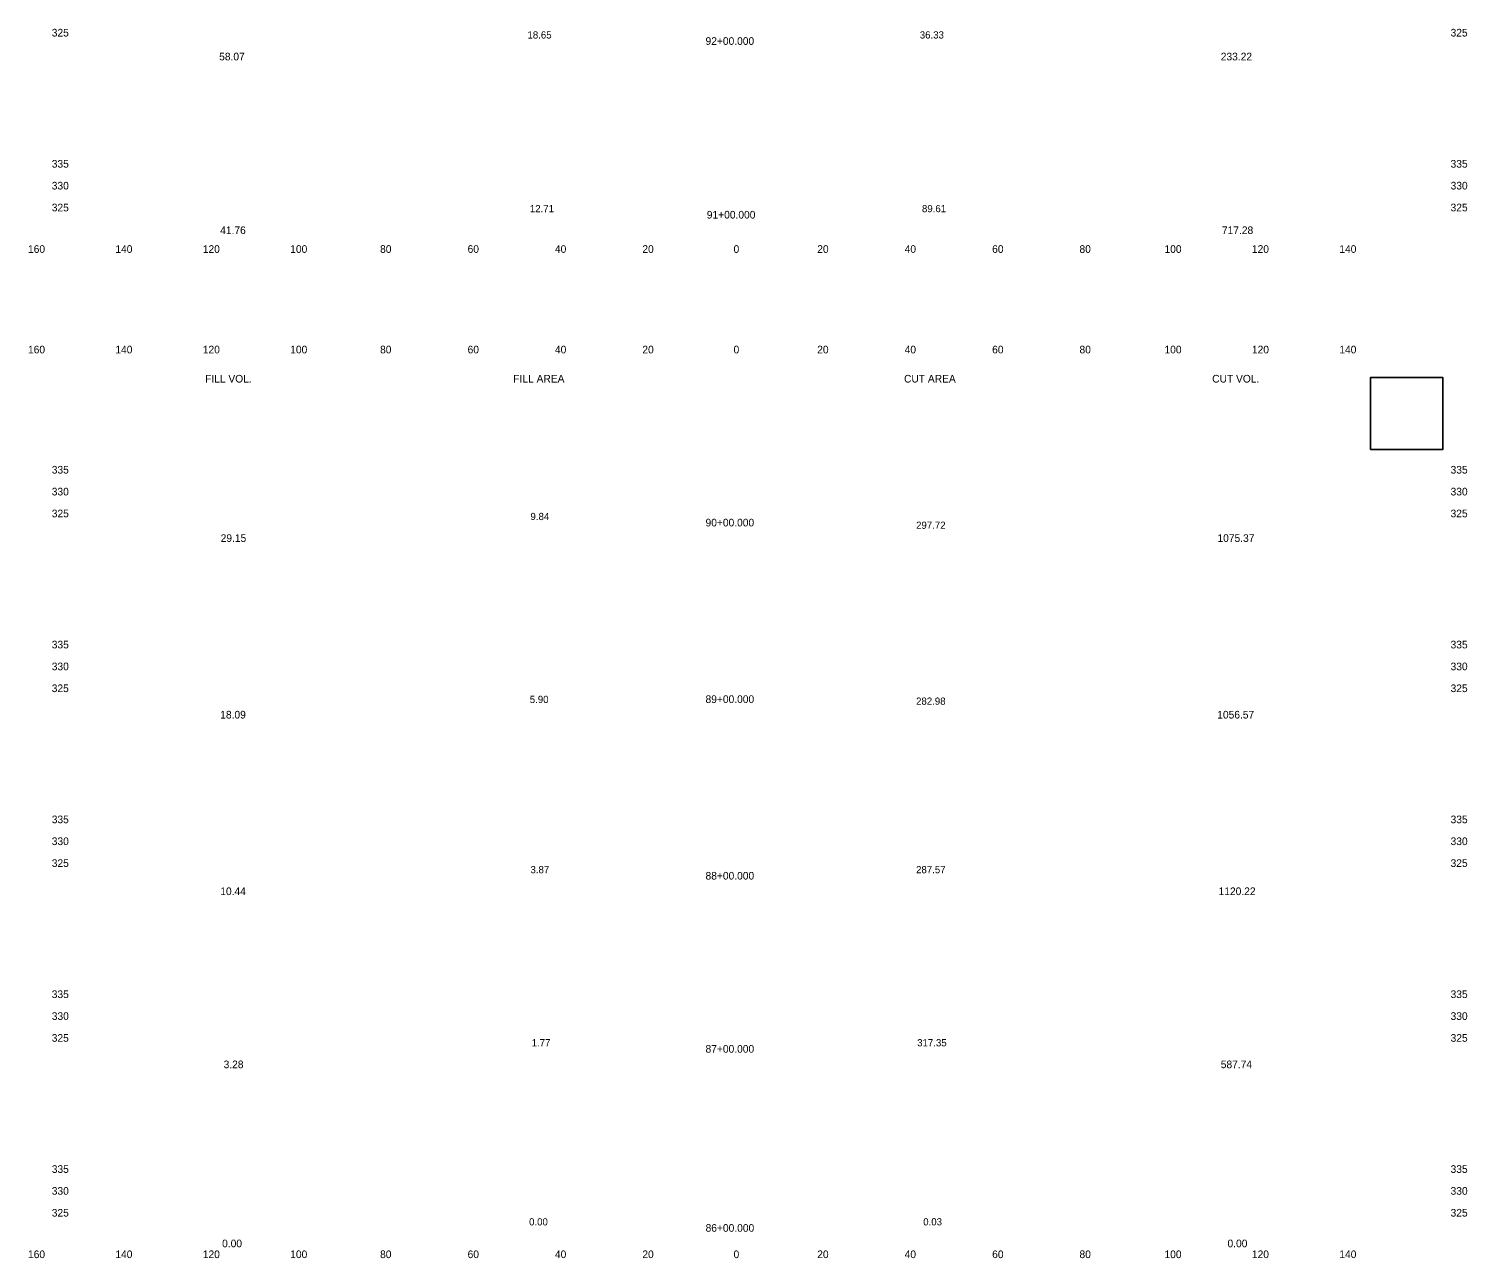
# Model space of a CAD drawing. Extents: x 21477 to 21806, y 6470 to 11049.
# Drawn here: x 21477.1 to 21806.1, y 6470.3 to 6751.6 of the extents above; entities that cross this region are included whole.
import ezdxf

# ---------------------------------------------------------------- set-up
doc = ezdxf.new("R2010")
doc.units = 0
for name, color, linetype in [('SHEET_CONSULTANT_STAMP', 7, 'Continuous'), ('XS_SHEET_EW_TX_AREA', 7, 'Continuous'), ('XS_SHEET_EW_TX_VOLUME', 7, 'Continuous'), ('XS_SHEET_LABELS_ELEVATION', 7, 'Continuous'), ('XS_SHEET_LABELS_OFFSET', 7, 'Continuous'), ('XS_SHEET_LABELS_STATION', 7, 'Continuous'), ('XS_SHEET_TX', 7, 'Continuous')]:
    doc.layers.add(name, color=color, linetype=linetype)

msp = doc.modelspace()

# ---------------------------------------------------------------- linework, layer by layer
at = {"layer": 'SHEET_CONSULTANT_STAMP'}
msp.add_lwpolyline([(21784.04, 6655.34), (21800.54, 6655.34), (21800.54, 6671.84), (21784.04, 6671.84)], close=True, dxfattribs=at)

# ---------------------------------------------------------------- texts
at = {"layer": 'XS_SHEET_EW_TX_AREA'}
for s, p in [(' 18.65 ', (21590.55, 6749.38)), (' 36.33 ', (21680.3, 6749.38)), (' 12.71 ', (21591.1, 6709.64)), (' 89.61 ', (21680.8, 6709.64)), (' 9.84 ', (21591.24, 6639.2)), (' 297.72 ', (21679.45, 6637.2)), (' 5.90 ', (21591.08, 6597.35)), (' 282.98 ', (21679.45, 6596.95)), (' 3.87 ', (21591.24, 6558.4)), (' 287.57 ', (21679.45, 6558.4)), (' 1.77 ', (21591.5, 6518.79)), (' 317.35 ', (21679.7, 6518.79)), (' 0.00 ', (21590.92, 6477.82)), (' 0.03 ', (21681.09, 6477.82))]:
    msp.add_text(s, height=1.65, dxfattribs=at).set_placement(p)
at = {"layer": 'XS_SHEET_EW_TX_VOLUME'}
for s, p in [(' 58.07 ', (21519.98, 6744.38)), (' 233.22 ', (21749.12, 6744.38)), (' 41.76 ', (21520.22, 6704.64)), (' 717.28 ', (21749.38, 6704.64)), (' 29.15 ', (21520.33, 6634.2)), (' 1075.37 ', (21748.36, 6634.2)), (' 18.09 ', (21520.23, 6593.8)), (' 1056.57 ', (21748.31, 6593.8)), (' 10.44 ', (21520.24, 6553.4)), (' 1120.22 ', (21748.62, 6553.4)), (' 3.28 ', (21521, 6513.79)), (' 587.74 ', (21749.12, 6513.79)), (' 0.00 ', (21520.66, 6472.82)), (' 0.00 ', (21750.66, 6472.82))]:
    msp.add_text(s, height=1.75, dxfattribs=at).set_placement(p)
at = {"layer": 'XS_SHEET_LABELS_ELEVATION'}
for s, p in [('  325  ', (21481.04, 6749.84)), ('  325  ', (21801.04, 6749.84)), ('  335  ', (21481.04, 6719.84)), ('  335  ', (21801.04, 6719.84)), ('  330  ', (21481.04, 6714.84)), ('  330  ', (21801.04, 6714.84)), ('  325  ', (21481.04, 6709.84)), ('  325  ', (21801.04, 6709.84)), ('  335  ', (21481.04, 6649.84)), ('  335  ', (21801.04, 6649.84)), ('  330  ', (21481.04, 6644.84)), ('  330  ', (21801.04, 6644.84)), ('  325  ', (21481.04, 6639.84)), ('  325  ', (21801.04, 6639.84)), ('  335  ', (21481.04, 6609.84)), ('  335  ', (21801.04, 6609.84)), ('  330  ', (21481.04, 6604.84)), ('  330  ', (21801.04, 6604.84)), ('  325  ', (21481.04, 6599.84)), ('  325  ', (21801.04, 6599.84)), ('  335  ', (21481.04, 6569.84)), ('  335  ', (21801.04, 6569.84)), ('  330  ', (21481.04, 6564.84)), ('  330  ', (21801.04, 6564.84)), ('  325  ', (21481.04, 6559.84)), ('  325  ', (21801.04, 6559.84)), ('  335  ', (21481.04, 6529.84)), ('  335  ', (21801.04, 6529.84)), ('  330  ', (21481.04, 6524.84)), ('  330  ', (21801.04, 6524.84)), ('  325  ', (21481.04, 6519.84)), ('  325  ', (21801.04, 6519.84)), ('  335  ', (21481.04, 6489.84)), ('  335  ', (21801.04, 6489.84)), ('  330  ', (21481.04, 6484.84)), ('  330  ', (21801.04, 6484.84)), ('  325  ', (21481.04, 6479.84)), ('  325  ', (21801.04, 6479.84))]:
    msp.add_text(s, height=1.75, dxfattribs=at).set_placement(p)
at = {"layer": 'XS_SHEET_LABELS_OFFSET'}
for s, p in [('  160  ', (21475.6, 6700.34)), ('  140  ', (21495.59, 6700.34)), ('  120  ', (21515.59, 6700.34)), ('  100  ', (21535.59, 6700.34)), ('  80  ', (21556.15, 6700.34)), ('  60  ', (21576.17, 6700.34)), ('  40  ', (21596.15, 6700.34)), ('  20  ', (21616.15, 6700.34)), ('  0  ', (21637.01, 6700.34)), ('  0  ', (21637.01, 6700.34)), ('  20  ', (21656.15, 6700.34)), ('  40  ', (21676.15, 6700.34)), ('  60  ', (21696.17, 6700.34)), ('  80  ', (21716.15, 6700.34)), ('  100  ', (21735.59, 6700.34)), ('  120  ', (21755.59, 6700.34)), ('  140  ', (21775.59, 6700.34)), ('  160  ', (21475.6, 6677.34)), ('  140  ', (21495.59, 6677.34)), ('  120  ', (21515.59, 6677.34)), ('  100  ', (21535.59, 6677.34)), ('  80  ', (21556.15, 6677.34)), ('  60  ', (21576.17, 6677.34)), ('  40  ', (21596.15, 6677.34)), ('  20  ', (21616.15, 6677.34)), ('  0  ', (21637.01, 6677.34)), ('  0  ', (21637.01, 6677.34)), ('  20  ', (21656.15, 6677.34)), ('  40  ', (21676.15, 6677.34)), ('  60  ', (21696.17, 6677.34)), ('  80  ', (21716.15, 6677.34)), ('  100  ', (21735.59, 6677.34)), ('  120  ', (21755.59, 6677.34)), ('  140  ', (21775.59, 6677.34)), ('  160  ', (21475.6, 6470.34)), ('  140  ', (21495.59, 6470.34)), ('  120  ', (21515.59, 6470.34)), ('  100  ', (21535.59, 6470.34)), ('  80  ', (21556.15, 6470.34)), ('  60  ', (21576.17, 6470.34)), ('  40  ', (21596.15, 6470.34)), ('  20  ', (21616.15, 6470.34)), ('  0  ', (21637.01, 6470.34)), ('  0  ', (21637.01, 6470.34)), ('  20  ', (21656.15, 6470.34)), ('  40  ', (21676.15, 6470.34)), ('  60  ', (21696.17, 6470.34)), ('  80  ', (21716.15, 6470.34)), ('  100  ', (21735.59, 6470.34)), ('  120  ', (21755.59, 6470.34)), ('  140  ', (21775.59, 6470.34))]:
    msp.add_text(s, height=1.75, dxfattribs=at).set_placement(p)
at = {"layer": 'XS_SHEET_LABELS_STATION'}
for s, p in [('  92+00.000  ', (21630.6, 6747.93)), ('  91+00.000  ', (21630.89, 6708.19)), ('  90+00.000  ', (21630.6, 6637.75)), ('  89+00.000  ', (21630.6, 6597.35)), ('  88+00.000  ', (21630.6, 6556.95)), ('  87+00.000  ', (21630.6, 6517.34)), ('  86+00.000  ', (21630.61, 6476.37))]:
    msp.add_text(s, height=1.75, dxfattribs=at).set_placement(p)
at = {"layer": 'XS_SHEET_TX'}
for s, p in [('FILL VOL.', (21517.41, 6670.67)), ('FILL AREA', (21587.92, 6670.67)), ('CUT AREA', (21677.31, 6670.67)), ('CUT VOL.', (21747.8, 6670.67))]:
    msp.add_text(s, height=1.75, dxfattribs=at).set_placement(p)

doc.saveas('drawing.dxf')
